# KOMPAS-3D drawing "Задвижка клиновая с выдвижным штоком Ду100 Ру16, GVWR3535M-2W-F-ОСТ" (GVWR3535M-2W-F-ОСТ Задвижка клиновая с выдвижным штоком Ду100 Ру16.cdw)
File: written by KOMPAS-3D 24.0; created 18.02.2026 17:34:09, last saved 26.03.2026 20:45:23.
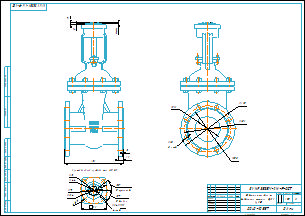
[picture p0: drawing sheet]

Document properties: Автор: R2D2; Форматы листов документа: A2; Полное имя файла: GVWR3535M-2W-F-ОСТ Задвижка клиновая с выдвижным штоком Ду100 Ру16.m3d; Масса: 25.5; Наименование: Задвижка клиновая с выдвижным штоком Ду100 Ру16; Количество листов документа: 1; Примечание: D040-10557

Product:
- Part/product: Задвижка клиновая с выдвижным штоком Ду100 Ру16  | designation GVWR3535M-2W-F-ОСТ
    Масса: 25.5
    Раздел спецификации: Прочие изделия
    Примечание: D040-10557

Views: Проекционный вид 3
Referenced files in E:\Работа\Зайцев\Для компаса\: чертеж DN.ru А3.cdt
Referenced files in E:\Работа\Зайцев\GVWR3535M-2W-F-ОСТ Задвижка клиновая 30нж941нж DN.ru Ду50-200 Ру16\исходные данные\DN100\dn100\: GVWR3535M-2W-F-ОСТ Задвижка клиновая с выдвижным штоком Ду100 Ру16.m3d
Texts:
  Присоединение привода тип АК (А)
  чертеж DN.ru А3.cdt
  Задвижка клиновая с
  выдвижным штоком Ду100
  Ру16
  GVWR3535M-2W-F-ОСТ
  Задвижка клиновая с выдвижным штоком Ду100 Ру16
  GVWR3535M-2W-F-ОСТ Задвижка клиновая с выдвижным штоком Ду100 Ру16
Dimensions and other numbers on the sheet: 100; 5 кулачков; 5 впадин; 14 (М12); 4 отв.; 13,5; 104; 70; 44; 32; 1:2; 0; 1; 2; 25,5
